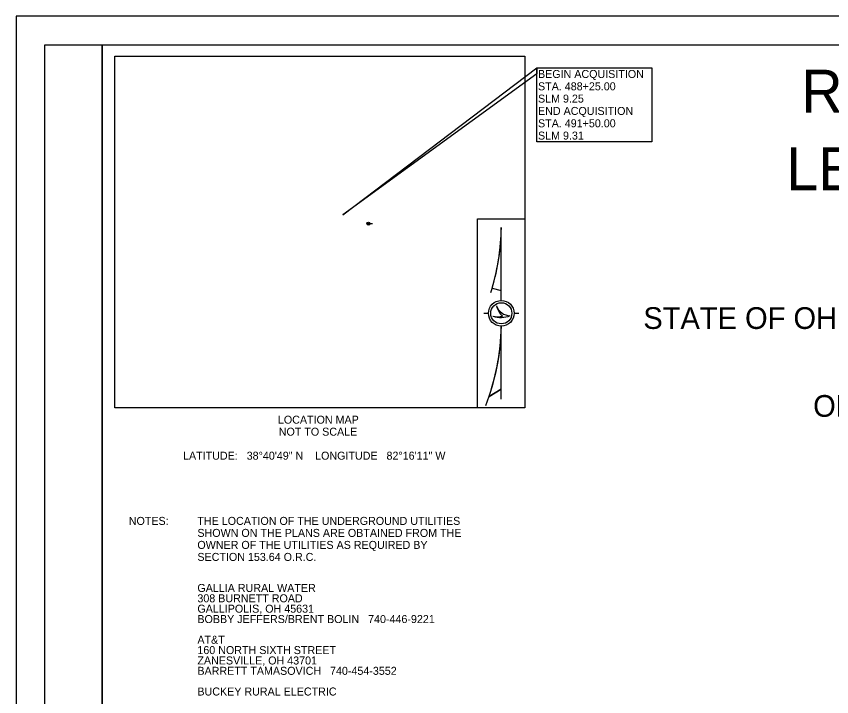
# Model space of a CAD drawing. Extents: x 0 to 34.3, y -4.1 to 22.
# Drawn here: x 0 to 14.26, y 10.1 to 22 of the extents above; entities that cross this region are included whole.
import ezdxf

# ---------------------------------------------------------------- set-up
doc = ezdxf.new("R2010")
doc.units = 0
for name, color, linetype in [('GM_X_Adjacent_County', 7, 'Continuous'), ('GM_X_County', 7, 'Continuous'), ('GM_X_Section', 7, 'Continuous'), ('GM_X_Township', 7, 'Continuous')]:
    doc.layers.add(name, color=color, linetype=linetype)

msp = doc.modelspace()

# ---------------------------------------------------------------- linework, layer by layer
at = {"layer": 'GM_X_Adjacent_County'}
for p, q in [((6.133, 18.372), (6.185, 18.372)), ((6.159, 18.372), (6.227, 18.372))]:
    msp.add_line(p, q, dxfattribs=at)
for points in [[(9.106, 20.995), (5.711, 18.527), (9.106, 21.098)], [(9.106, 21.098), (11.114, 21.098), (11.114, 19.805), (9.106, 19.805)], [(8.896, 15.152), (8.068, 15.152), (8.068, 18.456), (8.896, 18.456)]]:
    msp.add_lwpolyline(points, close=True, dxfattribs=at)
msp.add_circle((6.159, 18.372), 0.026, dxfattribs=at)
at = {"layer": 'GM_X_County'}
for points in [[(0.5, 21.5), (1.5, 21.5), (1.5, 0.5), (0.5, 0.5)], [(1.5, 21.5), (33.5, 21.5), (33.5, 0.5), (1.5, 0.5)], [(1.724, 21.3), (8.896, 21.3), (8.896, 15.152), (1.724, 15.152)]]:
    msp.add_lwpolyline(points, close=True, dxfattribs=at)
at = {"layer": 'GM_X_Section'}
msp.add_lwpolyline([(0, 0), (34, 0), (34, 22), (0, 22)], close=True, dxfattribs=at)
at = {"layer": 'GM_X_Township'}
for p, q in [((8.482, 17.029), (8.482, 18.304)), ((8.322, 17.244), (8.482, 17.201)), ((8.177, 16.804), (8.257, 16.804)), ((8.707, 16.804), (8.787, 16.804)), ((8.482, 15.304), (8.482, 16.579)), ((8.482, 15.479), (8.267, 15.35))]:
    msp.add_line(p, q, dxfattribs=at)
for points in [[(8.321, 17.245), (8.322, 17.244), (8.482, 17.201), (8.482, 18.304)], [(8.267, 15.35), (8.482, 15.479), (8.482, 16.579)]]:
    msp.add_lwpolyline(points, dxfattribs=at)
for radius in [0.225, 0.185]:
    msp.add_circle((8.482, 16.804), radius, dxfattribs=at)
for centre, radius, start, end in [((4.54, 18.359), 3.943, 342.4153, 359.1947), ((4.54, 18.359), 3.943, 343.5754, 359.1947), ((8.639, 17.017), 0.255, 199.1575, 269.3709), ((8.748, 17.013), 0.358, 192.8556, 227.3141), ((8.471, 17.183), 0.452, 252.4874, 291.486), ((8.427, 17.315), 0.571, 260.7277, 277.8734), ((4.54, 16.634), 3.943, 338.5054, 359.1947), ((4.54, 16.634), 3.943, 340.9936, 359.1947)]:
    msp.add_arc(centre, radius, start, end, dxfattribs=at)

# ---------------------------------------------------------------- texts
at = {"layer": 'GM_X_Adjacent_County'}
for s, height, p in [('BEGIN ACQUISITION  ', 0.14, (9.124, 20.921)), ('STA. 488+25.00 ', 0.14, (9.124, 20.705)), ('SLM 9.25', 0.14, (9.124, 20.49)), ('END ACQUISITION', 0.14, (9.124, 20.274)), ('STA. 491+50.00 ', 0.14, (9.124, 20.058)), ('SLM 9.31', 0.14, (9.124, 19.843)), ('1', 0.00328, (6.158, 18.379)), ('Drawing', 0.00328, (6.192, 18.379)), ('CUSTOM 1:5280', 0.00328, (6.192, 18.362)), ('LOCATION MAP', 0.14, (4.575, 14.872)), ('NOT TO SCALE', 0.14, (4.59, 14.662)), ('LATITUDE:   38°40\'49" N    LONGITUDE   82°16\'11" W', 0.14, (2.916, 14.242)), ('NOTES:', 0.14, (1.967, 13.101)), ('THE LOCATION OF THE UNDERGROUND UTILITIES', 0.14, (3.167, 13.101)), ('SHOWN ON THE PLANS ARE OBTAINED FROM THE', 0.14, (3.167, 12.891)), ('OWNER OF THE UTILITIES AS REQUIRED BY', 0.14, (3.167, 12.681)), ('SECTION 153.64 O.R.C.', 0.14, (3.167, 12.471)), ('GALLIA RURAL WATER', 0.14, (3.167, 11.928)), ('308 BURNETT ROAD', 0.14, (3.167, 11.747)), ('GALLIPOLIS, OH 45631', 0.14, (3.167, 11.565)), ('BOBBY JEFFERS/BRENT BOLIN   740-446-9221', 0.14, (3.167, 11.384)), ('AT&T', 0.14, (3.167, 11.022)), ('160 NORTH SIXTH STREET', 0.14, (3.167, 10.841)), ('ZANESVILLE, OH 43701', 0.14, (3.167, 10.659)), ('BARRETT TAMASOVICH   740-454-3552', 0.14, (3.167, 10.478)), ('BUCKEY RURAL ELECTRIC', 0.14, (3.167, 10.116))]:
    msp.add_text(s, height=height, dxfattribs=at).set_placement(p)
at = {"layer": 'GM_X_Township'}
for s, height, p in [('RIGHT OF WAY', 0.75, (13.727, 20.316)), ('LEGEND SHEET', 0.75, (13.468, 18.957)), ('STATE OF OHIO, GALLIA COUNTY, HARRISON TWP.,', 0.38, (10.966, 16.53)), ('OHIO COMPANY PURCHASE', 0.38, (13.936, 14.993))]:
    msp.add_text(s, height=height, dxfattribs=at).set_placement(p)

doc.saveas('drawing.dxf')
